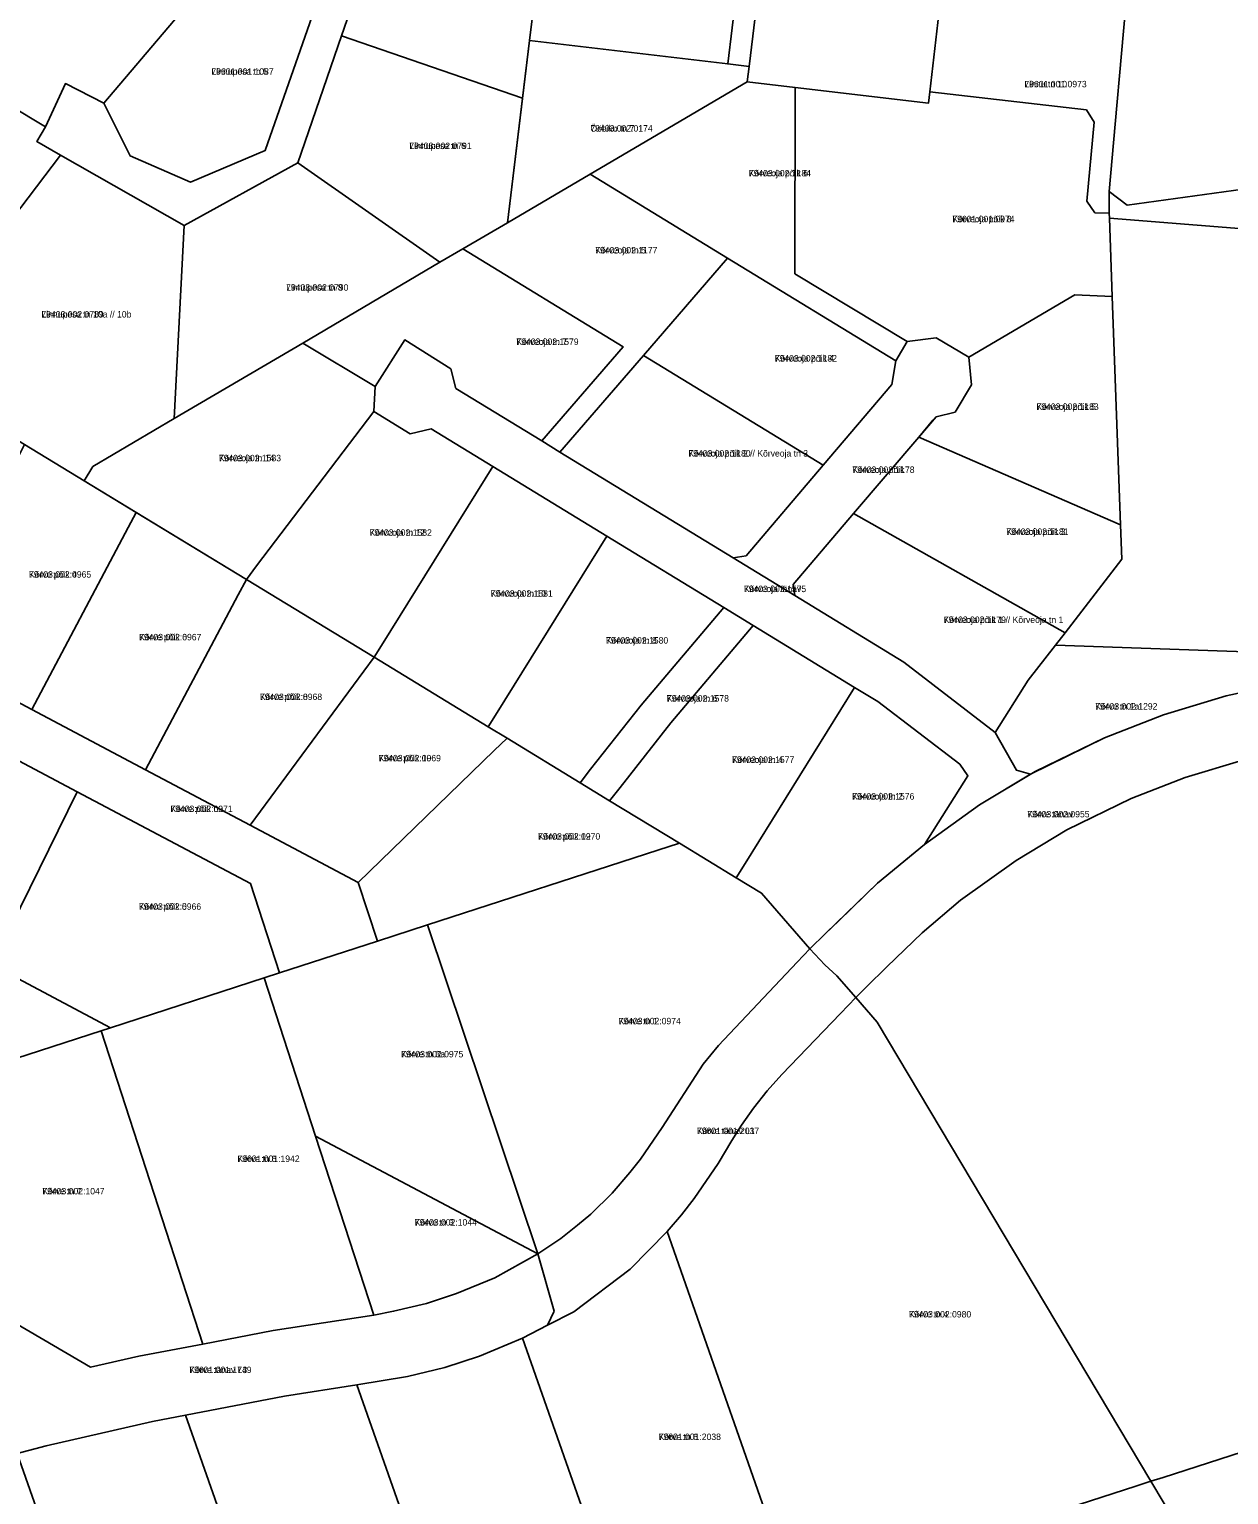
# Model space of a CAD drawing. Extents: x 625111 to 706696, y 6474150 to 6504223.
# Drawn here: x 661022.2 to 661301.7, y 6478536.3 to 6478877.8 of the extents above; entities that cross this region are included whole.
import ezdxf

# ---------------------------------------------------------------- set-up
doc = ezdxf.new("R2010")
doc.units = 0
for name, color, linetype in [('L_AADRESS', 7, 'Continuous'), ('PIIR', 7, 'Continuous'), ('TUNNUS', 7, 'Continuous')]:
    doc.layers.add(name, color=color, linetype=linetype)

msp = doc.modelspace()

# ---------------------------------------------------------------- linework, layer by layer
at = {"layer": 'PIIR'}
for points in [[(661026.03, 6478855.14), (661030.64, 6478865.17), (661039.56, 6478860.62), (661045.71, 6478848.35), (661059.83, 6478842.21), (661077.18, 6478849.55), (661089.77, 6478885.68), (661098.53, 6478911.11), (661111.33, 6478947.66), (661113.02, 6478952.48), (661121.18, 6478951.56), (661107.42, 6478912.21), (661095, 6478876.28), (661084.77, 6478846.71), (661058.3, 6478832.1), (661029.5, 6478848.51), (661024, 6478851.68)], [(661198.86, 6478942.56), (661189.95, 6478869.2), (661184.99, 6478869.79), (661188.05, 6478895.03), (661190.97, 6478919.07), (661193.9, 6478943.13)], [(661198.86, 6478942.56), (661239.94, 6478939.18), (661235.54, 6478893.68), (661232.09, 6478863.28), (661231.78, 6478860.65), (661200.69, 6478864.31), (661189.52, 6478865.63), (661189.95, 6478869.2)], [(661318.09, 6478932.04), (661314.22, 6478890.56), (661309.62, 6478841.19), (661278.09, 6478836.86), (661273.88, 6478840.05), (661275.3, 6478855.69), (661278.2, 6478888.78), (661282.75, 6478936.59)], [(661107.42, 6478912.21), (661141.86, 6478900.38), (661138.8, 6478875.23), (661137.15, 6478861.77), (661095, 6478876.28)], [(661067.24, 6478893.28), (661039.56, 6478860.62), (661030.64, 6478865.17), (661026.03, 6478855.14), (660999.96, 6478870.7), (661034.15, 6478904.56)], [(661188.05, 6478895.03), (661184.99, 6478869.79), (661138.8, 6478875.23), (661141.86, 6478900.38)], [(661039.56, 6478860.62), (661067.24, 6478893.28), (661089.77, 6478885.68), (661077.18, 6478849.55), (661059.83, 6478842.21), (661045.71, 6478848.35)], [(661256.72, 6478890.94), (661278.2, 6478888.78), (661275.3, 6478855.69), (661273.88, 6478840.05), (661273.91, 6478834.96), (661270.54, 6478835.05), (661268.67, 6478837.79), (661270.36, 6478856.2), (661268.57, 6478859.1), (661232.09, 6478863.28), (661235.54, 6478893.68)], [(661137.15, 6478861.77), (661133.65, 6478832.76), (661123.23, 6478826.64), (661117.91, 6478823.55), (661084.77, 6478846.71), (661095, 6478876.28)], [(661184.99, 6478869.79), (661189.95, 6478869.2), (661189.52, 6478865.63), (661152.93, 6478844.1), (661133.65, 6478832.76), (661138.8, 6478875.23)], [(660999.96, 6478870.7), (661026.03, 6478855.14), (661024, 6478851.68), (661029.5, 6478848.51), (660994.14, 6478801.97), (660991.81, 6478798.9), (660960.45, 6478817.99), (660952.37, 6478822.91), (660954.3, 6478826.09)], [(661152.93, 6478844.1), (661189.52, 6478865.63), (661200.69, 6478864.31), (661200.64, 6478820.84), (661226.83, 6478805.03), (661224.17, 6478800.59), (661184.97, 6478824.51)], [(661231.78, 6478860.65), (661232.09, 6478863.28), (661268.57, 6478859.1), (661270.36, 6478856.2), (661268.67, 6478837.79), (661270.54, 6478835.05), (661273.91, 6478834.96), (661273.97, 6478833.84), (661274.6, 6478815.59), (661265.86, 6478815.95), (661241.14, 6478801.43), (661233.56, 6478805.93), (661226.83, 6478805.03), (661200.64, 6478820.84), (661200.69, 6478864.31)], [(660994.14, 6478801.97), (661029.5, 6478848.51), (661058.3, 6478832.1), (661055.96, 6478787.12), (661037.01, 6478775.91), (661034.99, 6478772.61), (661021.08, 6478781.08), (661008.03, 6478789.02), (660992.69, 6478798.36), (660991.81, 6478798.9)], [(661084.77, 6478846.71), (661117.91, 6478823.55), (661085.96, 6478804.71), (661055.96, 6478787.12), (661058.3, 6478832.1)], [(661273.88, 6478840.05), (661278.09, 6478836.86), (661309.62, 6478841.19), (661364.93, 6478849.03), (661365.44, 6478849.1), (661369.8, 6478819.84), (661375.16, 6478797.56), (661393.95, 6478736.13), (661373.86, 6478741.54), (661351.72, 6478776.24), (661353.72, 6478827.45), (661273.97, 6478833.84), (661273.91, 6478834.96)], [(661123.23, 6478826.64), (661133.65, 6478832.76), (661152.93, 6478844.1), (661184.97, 6478824.51), (661165.37, 6478801.84), (661145.89, 6478779.29), (661141.63, 6478781.9), (661160.58, 6478803.83)], [(661273.97, 6478833.84), (661353.72, 6478827.45), (661351.72, 6478776.24), (661373.86, 6478741.54), (661393.95, 6478736.13), (661385.56, 6478729.95), (661261.37, 6478734.3), (661263.6, 6478737.18), (661276.83, 6478754.33), (661276.54, 6478762.31), (661274.6, 6478815.59)], [(661123.23, 6478826.64), (661160.58, 6478803.83), (661141.63, 6478781.9), (661121.6, 6478794.13), (661120.47, 6478798.68), (661109.72, 6478805.45), (661102.81, 6478794.55), (661085.96, 6478804.71), (661117.91, 6478823.55)], [(661184.97, 6478824.51), (661224.17, 6478800.59), (661223.22, 6478795.06), (661207.24, 6478776.27), (661165.37, 6478801.84)], [(661241.14, 6478801.43), (661265.86, 6478815.95), (661274.6, 6478815.59), (661276.54, 6478762.31), (661229.52, 6478782.78), (661232.81, 6478786.69), (661233.53, 6478787.48), (661237.97, 6478788.6), (661241.8, 6478795)], [(661102.81, 6478794.55), (661109.72, 6478805.45), (661120.47, 6478798.68), (661121.6, 6478794.13), (661141.63, 6478781.9), (661145.89, 6478779.29), (661186.25, 6478754.63), (661200.62, 6478745.85), (661226.03, 6478730.32), (661247.34, 6478713.95), (661252.24, 6478705.15), (661255.58, 6478704.24), (661243.65, 6478697.07), (661230.83, 6478687.85), (661240.97, 6478703.81), (661239.11, 6478706.53), (661219.93, 6478721.16), (661214.55, 6478724.45), (661190.95, 6478738.87), (661184.04, 6478743.09), (661156.83, 6478759.71), (661130.24, 6478775.96), (661115.9, 6478784.72), (661110.97, 6478783.55), (661102.52, 6478788.75)], [(661186.25, 6478754.63), (661189.25, 6478755.11), (661207.24, 6478776.27), (661223.22, 6478795.06), (661224.17, 6478800.59), (661226.83, 6478805.03), (661233.56, 6478805.93), (661241.14, 6478801.43), (661241.8, 6478795), (661237.97, 6478788.6), (661233.53, 6478787.48), (661229.52, 6478782.78), (661214.33, 6478764.97), (661200.22, 6478748.41), (661200.62, 6478745.85)], [(661037.01, 6478775.91), (661055.96, 6478787.12), (661085.96, 6478804.71), (661102.81, 6478794.55), (661102.52, 6478788.75), (661075.15, 6478752.78), (661072.81, 6478749.58), (661034.99, 6478772.61)], [(661165.37, 6478801.84), (661207.24, 6478776.27), (661189.25, 6478755.11), (661186.25, 6478754.63), (661145.89, 6478779.29)], [(661075.15, 6478752.78), (661102.52, 6478788.75), (661110.97, 6478783.55), (661115.9, 6478784.72), (661130.24, 6478775.96), (661104.66, 6478734.8), (661102.59, 6478731.46), (661072.81, 6478749.58)], [(661214.33, 6478764.97), (661229.52, 6478782.78), (661276.54, 6478762.31), (661276.83, 6478754.33), (661263.59, 6478737.19)], [(660997.16, 6478732.88), (661019.3, 6478777.5), (661021.08, 6478781.08), (661034.99, 6478772.61), (661047.14, 6478765.21), (661045.26, 6478761.67), (661022.82, 6478719.26)], [(661104.66, 6478734.8), (661130.24, 6478775.96), (661156.83, 6478759.71), (661131.28, 6478718.59), (661129.19, 6478715.22), (661102.59, 6478731.46)], [(661022.82, 6478719.26), (661045.26, 6478761.67), (661047.14, 6478765.21), (661072.81, 6478749.58), (661070.93, 6478746.03), (661049.33, 6478705.22)], [(661214.33, 6478764.97), (661263.59, 6478737.19), (661261.37, 6478734.3), (661255.03, 6478726.11), (661247.34, 6478713.95), (661226.03, 6478730.32), (661200.62, 6478745.85), (661200.22, 6478748.41)], [(661131.28, 6478718.59), (661156.83, 6478759.71), (661184.04, 6478743.09), (661164.8, 6478720.33), (661153.01, 6478705.36), (661150.56, 6478702.22), (661133.55, 6478712.61), (661129.19, 6478715.22)], [(661049.33, 6478705.22), (661070.93, 6478746.03), (661072.81, 6478749.58), (661102.59, 6478731.46), (661100.2, 6478728.22), (661073.73, 6478692.3)], [(661153.01, 6478705.36), (661164.8, 6478720.33), (661184.04, 6478743.09), (661190.95, 6478738.87), (661171.75, 6478716.14), (661159.93, 6478701.13), (661157.43, 6478697.96), (661150.56, 6478702.22)], [(661159.93, 6478701.13), (661171.75, 6478716.14), (661190.95, 6478738.87), (661214.55, 6478724.45), (661189.07, 6478683.41), (661186.98, 6478680.07), (661173.73, 6478688.14), (661157.43, 6478697.96)], [(661261.37, 6478734.3), (661385.56, 6478729.95), (661382.19, 6478727.47), (661350.52, 6478728.62), (661332.69, 6478727.88), (661316.58, 6478725.79), (661301.17, 6478722.47), (661286.51, 6478718.06), (661272.81, 6478712.71), (661255.58, 6478704.24), (661252.24, 6478705.15), (661247.34, 6478713.95), (661255.03, 6478726.11)], [(660971.16, 6478680.21), (660992.72, 6478723.96), (660997.16, 6478732.88), (661022.82, 6478719.26), (661049.33, 6478705.22), (661073.73, 6478692.3), (661098.9, 6478678.98), (661103.34, 6478665.29), (661080.51, 6478657.88), (661073.75, 6478678.73), (661033.4, 6478700.09), (661002.47, 6478716.46), (660982.13, 6478675.44)], [(661073.73, 6478692.3), (661100.2, 6478728.22), (661102.59, 6478731.46), (661129.19, 6478715.22), (661133.55, 6478712.61), (661130.55, 6478709.76), (661098.9, 6478678.98)], [(661189.07, 6478683.41), (661214.55, 6478724.45), (661219.93, 6478721.16), (661239.11, 6478706.53), (661240.97, 6478703.81), (661230.83, 6478687.85), (661226.52, 6478684.27), (661219.92, 6478678.78), (661207.77, 6478667.08), (661204.08, 6478663.51), (661192.88, 6478676.49), (661186.98, 6478680.07)], [(661392.39, 6478717.8), (661391.21, 6478721.81), (661398.89, 6478720.51), (661442.48, 6478574.11), (661292.44, 6478524.53), (661283.6, 6478539.37), (661286.42, 6478540.29), (661428.57, 6478586.27), (661426.18, 6478600.9), (661422.33, 6478616.92), (661394.18, 6478711.67)], [(660982.13, 6478675.44), (661002.47, 6478716.46), (661033.4, 6478700.09), (661013.47, 6478659.79), (660991.97, 6478671.16)], [(661217.36, 6478654.67), (661222.03, 6478659.29), (661230.31, 6478667.26), (661239.26, 6478674.82), (661252.17, 6478684.11), (661264.02, 6478691.21), (661279.03, 6478698.5), (661291.57, 6478703.4), (661305.04, 6478707.45), (661319.21, 6478710.5), (661334.01, 6478712.42), (661350.54, 6478713.11), (661362.21, 6478712.66), (661380.5, 6478712.13), (661394.18, 6478711.67), (661422.33, 6478616.92), (661426.18, 6478600.9), (661428.57, 6478586.27), (661286.42, 6478540.29), (661283.6, 6478539.37), (661219.83, 6478646.4), (661214.85, 6478652.13)], [(661098.9, 6478678.98), (661130.55, 6478709.76), (661133.55, 6478712.61), (661150.56, 6478702.22), (661157.43, 6478697.96), (661173.73, 6478688.14), (661168.71, 6478686.52), (661115.03, 6478669.09), (661103.34, 6478665.29)], [(661013.47, 6478659.79), (661033.4, 6478700.09), (661073.75, 6478678.73), (661080.51, 6478657.88), (661076.94, 6478656.74), (661041.18, 6478645.1)], [(661115.03, 6478669.09), (661168.71, 6478686.52), (661173.73, 6478688.14), (661186.98, 6478680.07), (661192.88, 6478676.49), (661204.08, 6478663.51), (661201.14, 6478660.39), (661182.82, 6478640.94), (661179.25, 6478636.63), (661169.67, 6478621.81), (661164.63, 6478614.48), (661162.19, 6478611.33), (661158.07, 6478606.55), (661153.07, 6478601.61), (661150, 6478599.06), (661146.11, 6478596.01), (661140.77, 6478592.41)], [(660966.42, 6478643.75), (660982.13, 6478675.44), (660991.97, 6478671.16), (661013.47, 6478659.79), (661041.18, 6478645.1), (661038.95, 6478644.36), (660987.9, 6478627.82), (660972.85, 6478639.87)], [(661076.94, 6478656.74), (661080.51, 6478657.88), (661103.34, 6478665.29), (661115.03, 6478669.09), (661140.77, 6478592.41), (661088.94, 6478619.86)], [(661201.14, 6478660.39), (661204.08, 6478663.51), (661207.63, 6478659.8), (661210.42, 6478657.24), (661214.85, 6478652.13), (661211.29, 6478648.44), (661197.59, 6478634.24), (661194.19, 6478630.42), (661190.99, 6478626.34), (661188.23, 6478622.4), (661185.96, 6478618.79), (661182.74, 6478613.42), (661177.17, 6478605.28), (661174.18, 6478601.48), (661170.84, 6478597.58), (661162.23, 6478588.8), (661149.16, 6478578.91), (661143.02, 6478575.74), (661144.55, 6478579.02), (661140.77, 6478592.41), (661146.11, 6478596.01), (661150, 6478599.06), (661153.07, 6478601.61), (661158.07, 6478606.55), (661162.19, 6478611.33), (661164.63, 6478614.48), (661169.67, 6478621.81), (661179.25, 6478636.63), (661182.82, 6478640.94)], [(661041.18, 6478645.1), (661076.94, 6478656.74), (661088.94, 6478619.86), (661102.49, 6478578.13), (661079.05, 6478574.52), (661062.64, 6478571.36), (661038.95, 6478644.36)], [(661170.84, 6478597.58), (661174.18, 6478601.48), (661177.17, 6478605.28), (661182.74, 6478613.42), (661185.96, 6478618.79), (661188.23, 6478622.4), (661190.99, 6478626.34), (661194.19, 6478630.42), (661197.59, 6478634.24), (661211.29, 6478648.44), (661214.85, 6478652.13), (661219.83, 6478646.4), (661283.6, 6478539.37), (661280.11, 6478538.25), (661214.09, 6478516.9), (661200.65, 6478512.59)], [(661038.95, 6478644.36), (661062.64, 6478571.36), (661047.76, 6478568.51), (661036.47, 6478565.99), (661019.27, 6478576.12), (661014.05, 6478590.57), (661008.99, 6478600.73), (661003.31, 6478609.82), (660995.76, 6478619.58), (660987.9, 6478627.82)], [(661088.94, 6478619.86), (661140.77, 6478592.41), (661130.73, 6478586.83), (661121.77, 6478583.12), (661114.82, 6478580.84), (661107.11, 6478579), (661102.49, 6478578.13)], [(661162.23, 6478588.8), (661170.84, 6478597.58), (661200.65, 6478512.59), (661162.59, 6478500.38), (661137.15, 6478572.71), (661143.02, 6478575.74), (661149.16, 6478578.91)], [(661127.16, 6478568.57), (661137.15, 6478572.71), (661162.59, 6478500.38), (661124.46, 6478488.13), (661098.56, 6478561.83), (661110.35, 6478563.84), (661119.04, 6478565.91)], [(661081.69, 6478559.21), (661098.56, 6478561.83), (661124.46, 6478488.13), (661106.32, 6478482.34), (661099.46, 6478479.87), (661086.57, 6478475.33), (661058.63, 6478554.81)], [(661058.63, 6478554.81), (661086.57, 6478475.33), (661048.84, 6478462.08), (661019.39, 6478545.82), (661026.12, 6478547.66), (661050.95, 6478553.34)], [(661019.39, 6478545.82), (661048.84, 6478462.08), (661011.1, 6478448.82), (660981.01, 6478534.39), (661003.5, 6478541.47)], [(661106.32, 6478482.34), (661124.46, 6478488.13), (661162.59, 6478500.38), (661200.65, 6478512.59), (661214.09, 6478516.9), (661280.11, 6478538.25), (661283.6, 6478539.37), (661292.44, 6478524.53), (661104.36, 6478462.88), (661101.57, 6478465.66), (661101.42, 6478467.13), (661102.95, 6478473.76)]]:
    msp.add_lwpolyline(points, close=True, dxfattribs=at)
for points in [[(661305.04, 6478707.45), (661291.57, 6478703.4), (661279.03, 6478698.5), (661264.02, 6478691.21), (661252.17, 6478684.11), (661239.26, 6478674.82), (661230.31, 6478667.26), (661222.03, 6478659.29), (661217.36, 6478654.67), (661214.85, 6478652.13), (661210.42, 6478657.24), (661207.63, 6478659.8), (661204.08, 6478663.51), (661207.77, 6478667.08), (661210.87, 6478670.06), (661219.92, 6478678.78), (661230.83, 6478687.85), (661243.65, 6478697.07), (661256.64, 6478704.85), (661272.81, 6478712.71), (661286.51, 6478718.06), (661301.17, 6478722.47), (661316.58, 6478725.79)], [(661019.27, 6478576.12), (661036.47, 6478565.99), (661047.76, 6478568.51), (661062.64, 6478571.36), (661079.05, 6478574.52), (661102.49, 6478578.13), (661107.11, 6478579), (661114.82, 6478580.84), (661121.77, 6478583.12), (661130.73, 6478586.83), (661140.77, 6478592.41), (661144.55, 6478579.02), (661143.02, 6478575.74), (661137.15, 6478572.71), (661127.16, 6478568.57), (661119.04, 6478565.91), (661110.35, 6478563.84), (661098.56, 6478561.83), (661081.68, 6478559.22), (661058.63, 6478554.81), (661050.95, 6478553.34), (661026.12, 6478547.66), (661019.39, 6478545.82)]]:
    msp.add_lwpolyline(points, dxfattribs=at)

# ---------------------------------------------------------------- texts
at = {"layer": 'L_AADRESS'}
for s, p in [('Linnupesa tn 5', (661064.67, 6478867.25)), ('Linnu tn 10', (661254.13, 6478864.32)), ('Ööbiku tn 7', (661152.99, 6478854)), ('Linnupesa tn 6', (661110.8, 6478849.92)), ('Kõrveoja põik 6', (661189.88, 6478843.55)), ('Kõrveoja põik 8', (661237.33, 6478832.87)), ('Kõrveoja tn 5', (661154.1, 6478825.59)), ('Linnupesa tn 8', (661082.08, 6478816.92)), ('Linnupesa tn 10a // 10b', (661025.05, 6478810.66)), ('Kõrveoja tn 7', (661135.73, 6478804.27)), ('Kõrveoja põik 4', (661195.94, 6478800.39)), ('Kõrveoja põik 5', (661256.93, 6478789.13)), ('Kõrveoja tn 14', (661066.39, 6478777.15)), ('Kõrveoja põik 2 // Kõrveoja tn 3', (661175.82, 6478778.24)), ('Kõrveoja põik', (661214.02, 6478774.43)), ('Kõrveoja tn 12', (661101.53, 6478759.78)), ('Kõrveoja põik 3', (661249.9, 6478759.99)), ('Kõrve põik 4', (661022.15, 6478750.02)), ('Kõrveoja tn 10', (661129.71, 6478745.58)), ('Kõrveoja tänav', (661188.76, 6478746.65)), ('Kõrveoja põik 1 // Kõrveoja tn 1', (661235.32, 6478739.46)), ('Kõrve põik 6', (661047.82, 6478735.41)), ('Kõrveoja tn 8', (661156.61, 6478734.65)), ('Kõrve põik 8', (661075.96, 6478721.49)), ('Kõrveoja tn 6', (661170.76, 6478721.13)), ('Kõrve tn 1a', (661270.62, 6478719.27)), ('Kõrve põik 10', (661103.64, 6478707.2)), ('Kõrveoja tn 4', (661185.99, 6478706.84)), ('Kõrveoja tn 2', (661213.97, 6478698.29)), ('Kõrve põik L2', (661055.11, 6478695.38)), ('Kõrve tänav', (661254.8, 6478694.13)), ('Kõrve põik 12', (661140.77, 6478688.95)), ('Kõrve põik 5', (661047.77, 6478672.6)), ('Kõrve tn 1', (661159.55, 6478645.91)), ('Kõrve tn 3a', (661108.86, 6478638.2)), ('Kõrve tänav L1', (661177.81, 6478620.31)), ('Kõrve tn 5', (661070.72, 6478613.82)), ('Kõrve tn 7', (661025.27, 6478606.26)), ('Kõrve tn 3', (661112.03, 6478598.99)), ('Kõrve tn 4', (661227.22, 6478577.57)), ('Kõrve tänav L3', (661059.52, 6478564.6)), ('Kõrve tn 6', (661168.9, 6478549))]:
    msp.add_text(s, height=1.5, dxfattribs=at).set_placement(p)
at = {"layer": 'TUNNUS'}
for s, p in [('79601:001:1087', (661064.67, 6478867.25)), ('79601:001:0973', (661254.13, 6478864.32)), ('79403:002:0174', (661152.99, 6478854)), ('79403:002:0791', (661110.8, 6478849.92)), ('79403:002:1184', (661189.88, 6478843.55)), ('79601:001:0974', (661237.33, 6478832.87)), ('79403:002:1177', (661154.1, 6478825.59)), ('79403:002:0790', (661082.08, 6478816.92)), ('79403:002:0789', (661025.05, 6478810.66)), ('79403:002:1579', (661135.73, 6478804.27)), ('79403:002:1182', (661195.94, 6478800.39)), ('79403:002:1183', (661256.93, 6478789.13)), ('79403:002:1583', (661066.39, 6478777.15)), ('79403:002:1180', (661175.82, 6478778.24)), ('79403:002:1178', (661214.02, 6478774.43)), ('79403:002:1582', (661101.53, 6478759.78)), ('79403:002:1181', (661249.9, 6478759.99)), ('79403:002:0965', (661022.15, 6478750.02)), ('79403:002:1581', (661129.71, 6478745.58)), ('79403:002:1575', (661188.76, 6478746.65)), ('79403:002:1179', (661235.32, 6478739.46)), ('79403:002:0967', (661047.82, 6478735.41)), ('79403:002:1580', (661156.61, 6478734.65)), ('79403:002:0968', (661075.96, 6478721.49)), ('79403:002:1578', (661170.76, 6478721.13)), ('79403:002:1292', (661270.62, 6478719.27)), ('79403:002:0969', (661103.64, 6478707.2)), ('79403:002:1577', (661185.99, 6478706.84)), ('79403:002:1576', (661213.97, 6478698.29)), ('79403:002:0971', (661055.11, 6478695.38)), ('79403:002:0955', (661254.8, 6478694.13)), ('79403:002:0970', (661140.77, 6478688.95)), ('79403:002:0966', (661047.77, 6478672.6)), ('79403:002:0974', (661159.55, 6478645.91)), ('79403:002:0975', (661108.86, 6478638.2)), ('79601:001:2037', (661177.81, 6478620.31)), ('79601:001:1942', (661070.72, 6478613.82)), ('79403:002:1047', (661025.27, 6478606.26)), ('79403:002:1044', (661112.03, 6478598.99)), ('79403:002:0980', (661227.22, 6478577.57)), ('79601:001:1749', (661059.52, 6478564.6)), ('79601:001:2038', (661168.9, 6478549))]:
    msp.add_text(s, height=1.5, dxfattribs=at).set_placement(p)

doc.saveas('drawing.dxf')
